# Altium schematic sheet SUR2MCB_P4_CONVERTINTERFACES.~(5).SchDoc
size 420 x 297 mm; Scale: 1:1; Обозначение документа: АБВГ.123456.001 Э3
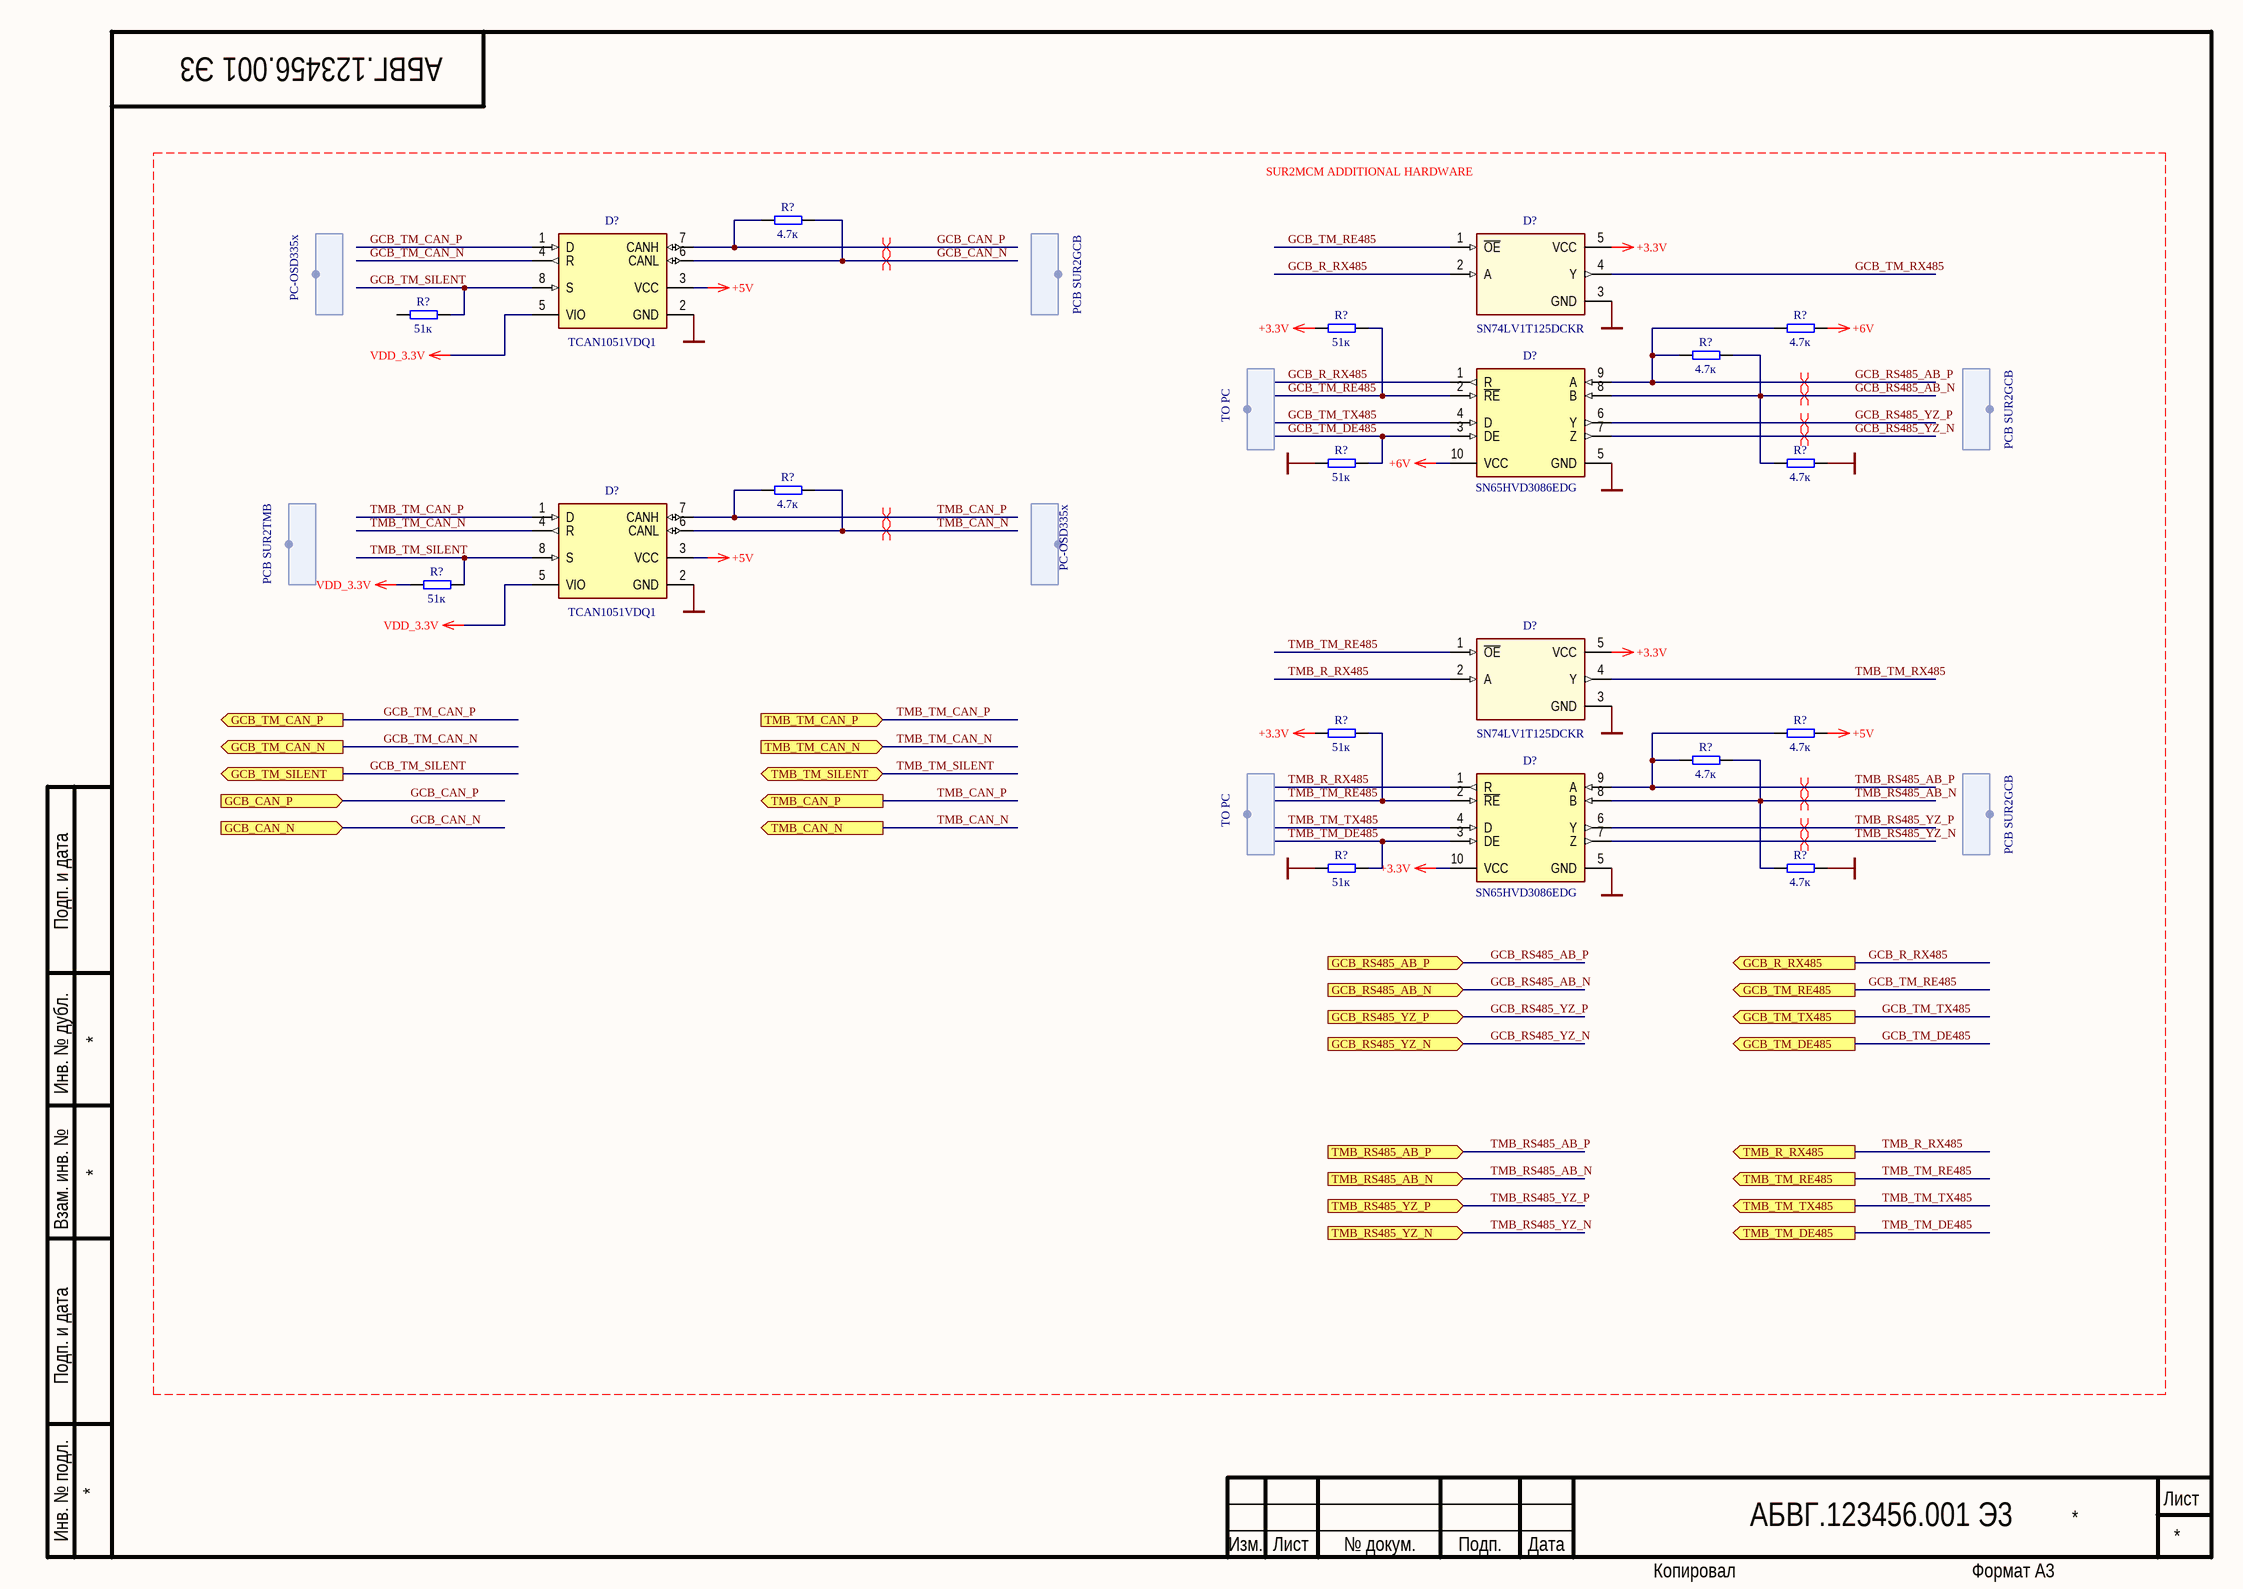
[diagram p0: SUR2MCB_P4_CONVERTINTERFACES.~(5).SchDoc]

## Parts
(Parts that share a designator on the sheet are numbered #1, #2 ... from top to bottom, then left to right.)
D?#1  value TCAN1051VDQ1  [SOP-8-3.9X5-1.27]
D?#2  value SN74LV1T125DCKR  [SOT353-5-1.25X2.1-0.65]
D?#3  value SN65HVD3086EDG  [MSOP-10-3X3-0.5]
D?#4  value TCAN1051VDQ1  [SOP-8-3.9X5-1.27]
D?#5  value SN74LV1T125DCKR  [SOT353-5-1.25X2.1-0.65]
D?#6  value SN65HVD3086EDG  [MSOP-10-3X3-0.5]
R?#1  value 4.7к  [R0603]
R?#2  value 51к  [R0603]
R?#3  value 51к  [R0603]
R?#4  value 4.7к  [R0603]
R?#5  value 4.7к  [R0603]
R?#6  value 51к  [R0603]
R?#7  value 4.7к  [R0603]
R?#8  value 4.7к  [R0603]
R?#9  value 51к  [R0603]
R?#10  value 51к  [R0603]
R?#11  value 4.7к  [R0603]
R?#12  value 4.7к  [R0603]
R?#13  value 51к  [R0603]
R?#14  value 4.7к  [R0603]

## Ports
GCB_CAN_N (in), GCB_CAN_P (in), GCB_R_RX485 (out), GCB_RS485_AB_N (in), GCB_RS485_AB_P (in), GCB_RS485_YZ_N (in), GCB_RS485_YZ_P (in), GCB_TM_CAN_N (out), GCB_TM_CAN_P (out), GCB_TM_DE485 (out), GCB_TM_RE485 (out), GCB_TM_SILENT (out), GCB_TM_TX485 (out), TMB_CAN_N (out), TMB_CAN_P (out), TMB_R_RX485 (out), TMB_RS485_AB_N (in), TMB_RS485_AB_P (in), TMB_RS485_YZ_N (in), TMB_RS485_YZ_P (in), TMB_TM_CAN_N (in), TMB_TM_CAN_P (in), TMB_TM_DE485 (out), TMB_TM_RE485 (out), TMB_TM_SILENT (bidir), TMB_TM_TX485 (out)

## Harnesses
PC-OSD335x: 
PCB SUR2GCB: 
PCB SUR2TMB: 
TO PC: 

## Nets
+3.3V: D?#2.5(VCC) D?#5.5(VCC) D?#6.10(VCC) R?#3.2 R?#10.2
+5V: D?#1.3(VCC) D?#4.3(VCC) R?#11.1
+6V: D?#3.10(VCC) R?#4.1
GND: D?#1.2(GND) D?#2.3(GND) D?#3.5(GND) D?#4.2(GND) D?#5.3(GND) D?#6.5(GND) R?#6.2 R?#7.1 R?#13.2 R?#14.1
VDD_3.3V: D?#1.5(VIO) D?#4.5(VIO) R?#9.2
GCB_CAN_N: D?#1.6(CANL) R?#1.1 ; port GCB_CAN_N
GCB_CAN_P: D?#1.7(CANH) R?#1.2 ; port GCB_CAN_P
GCB_R_RX485: D?#2.2(A) D?#3.1(R) ; port GCB_R_RX485
GCB_RS485_AB_N: D?#3.8(B) R?#5.1 R?#7.2 ; port GCB_RS485_AB_N
GCB_RS485_AB_P: D?#3.9(A) R?#4.2 R?#5.2 ; port GCB_RS485_AB_P
GCB_RS485_YZ_N: D?#3.7(Z) ; port GCB_RS485_YZ_N
GCB_RS485_YZ_P: D?#3.6(Y) ; port GCB_RS485_YZ_P
GCB_TM_CAN_N: D?#1.4(R) ; port GCB_TM_CAN_N
GCB_TM_CAN_P: D?#1.1(D) ; port GCB_TM_CAN_P
GCB_TM_DE485: D?#3.3(DE) R?#6.1 ; port GCB_TM_DE485
GCB_TM_RE485: D?#2.1(~{OE}) D?#3.2(~{RE}) R?#3.1 ; port GCB_TM_RE485
GCB_TM_RX485: D?#2.4(Y)
GCB_TM_SILENT: D?#1.8(S) R?#2.1 ; port GCB_TM_SILENT
GCB_TM_TX485: D?#3.4(D) ; port GCB_TM_TX485
TMB_CAN_N: D?#4.6(CANL) R?#8.1 ; port TMB_CAN_N
TMB_CAN_P: D?#4.7(CANH) R?#8.2 ; port TMB_CAN_P
TMB_R_RX485: D?#5.2(A) D?#6.1(R) ; port TMB_R_RX485
TMB_RS485_AB_N: D?#6.8(B) R?#12.1 R?#14.2 ; port TMB_RS485_AB_N
TMB_RS485_AB_P: D?#6.9(A) R?#11.2 R?#12.2 ; port TMB_RS485_AB_P
TMB_RS485_YZ_N: D?#6.7(Z) ; port TMB_RS485_YZ_N
TMB_RS485_YZ_P: D?#6.6(Y) ; port TMB_RS485_YZ_P
TMB_TM_CAN_N: D?#4.4(R) ; port TMB_TM_CAN_N
TMB_TM_CAN_P: D?#4.1(D) ; port TMB_TM_CAN_P
TMB_TM_DE485: D?#6.3(DE) R?#13.1 ; port TMB_TM_DE485
TMB_TM_RE485: D?#5.1(~{OE}) D?#6.2(~{RE}) R?#10.1 ; port TMB_TM_RE485
TMB_TM_RX485: D?#5.4(Y)
TMB_TM_SILENT: D?#4.8(S) R?#9.1 ; port TMB_TM_SILENT
TMB_TM_TX485: D?#6.4(D) ; port TMB_TM_TX485

Not connected (* = marked no-connect by the designer): R?#2 2

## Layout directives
differential pair: GCB_CAN_N, GCB_CAN_P, GCB_RS485_AB_N, GCB_RS485_AB_P, GCB_RS485_YZ_N, GCB_RS485_YZ_P, TMB_CAN_N, TMB_CAN_P, TMB_RS485_AB_N, TMB_RS485_AB_P, TMB_RS485_YZ_N, TMB_RS485_YZ_P

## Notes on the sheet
- SUR2MCM ADDITIONAL HARDWARE

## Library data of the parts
D?#1 D?#4 = TCAN1051VDQ1: CAN Transceiver 8-SOIC 5V; ValueManufacturer: Texas Instruments; PowerVoltage: 4.5V~5.5V; ValueDescription: TCAN1051VDQ1  CAN приемопередатчик 4.5V~5.5V  8-SOIC (3.90mm)
D?#2 D?#5 = SN74LV1T125DCKR: BUFFER GATE SHIFT LEVEL CMOS SC70-5; ValueManufacturer: Texas Instruments; PowerVoltage: 1.6V~5.5V; TechSpec: 50MHz; ValueDescription: SN74LV1T125DCKR Преобраз. логич. уровня 1.6V~5.5V  SC-70-5  50MHz
D?#3 D?#6 = SN65HVD3086EDG: RS422 RS485 FULL Transceiver 8-SOIC 5V; ValueManufacturer: Texas Instruments; PowerVoltage: 4.5V~5.5V; ValueDescription: SN65HVD3086EDG  FULL RS485/RS422 приемопередатчик 4.5V~5.5V  10-SOP (3.00mm)
R?#1 R?#4 R?#5 R?#7 R?#8 R?#11 R?#12 R?#14 = R-0603-5%: SMD 0603 0.1Вт ±5% 75В; ValueManufacturer: Panasonic; ValueManufacturerPartNumber: ERJ-3GE; PowerVoltage: 0.1Вт 75В; ValueDescription: 0603 (1608)  0.1Вт 75В  4.7кОм ±5%; ValueType: Chip Resistor
R?#2 R?#3 R?#6 R?#9 R?#10 R?#13 = R-0603-5%: SMD 0603 0.1Вт ±5% 75В; ValueManufacturer: Panasonic; ValueManufacturerPartNumber: ERJ-3GE; PowerVoltage: 0.1Вт 75В; ValueDescription: 0603 (1608)  0.1Вт 75В  51кОм ±5%; ValueType: Chip Resistor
